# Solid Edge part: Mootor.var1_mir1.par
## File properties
Author: jaanm
Template: Ansi Inch Part.par
Last saved by: jaanm
Revision: 3
Application: Solid Edge
Accuracy: 0,990
Username: jaanm
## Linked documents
Mootor.var1.par
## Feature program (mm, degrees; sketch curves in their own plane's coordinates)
part copy "CopiedPart_1"
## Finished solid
Body 1: solid body, 246 faces, 556 edges, 298 vertices, 2 separate solids.
  Faces by surface: plane 220, cylinder 21, cone 3, spline 2
  Edges by curve: line 416, ellipse 80, circle 33, intersection 26, spline 1
Bounding box of the edges (mm; curved faces can reach further): 450.120 x 650.000 x 369.541, from (-267.6032, -400, -184.7705) to (182.5166, 250, 184.7705).
Cylindrical faces by radius (mm): R5 x16, R33.9209 x1, R100 x1, R110 x1, R115 x1, R125 x1
Conical faces (half-angle, radius in mm at the cone's reference point): 45 deg R115 x1, 45 deg R120 x1, 45 deg R125 x1
Planar faces by outward normal: +x 3, +y 6, +z 3, -x 4, -y 4, -z 3, oblique 197
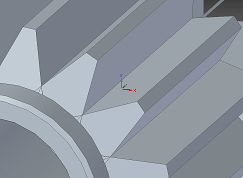
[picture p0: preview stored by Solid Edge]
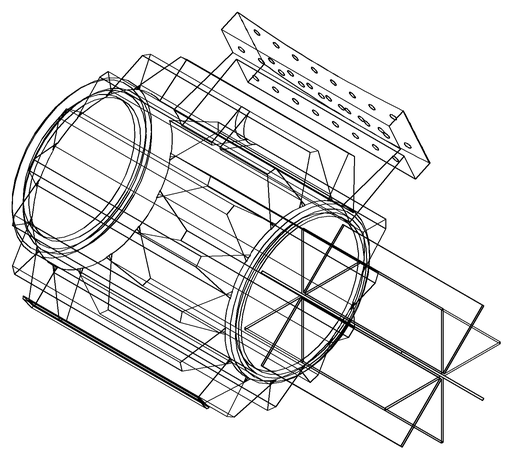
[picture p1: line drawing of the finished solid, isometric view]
